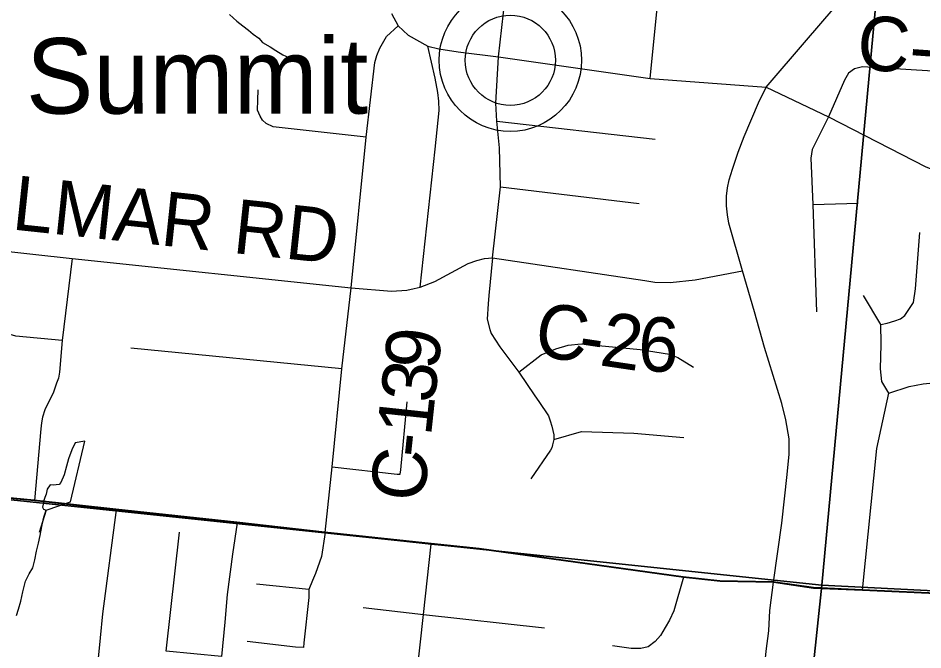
# Model space of a CAD drawing. Extents: x 0 to 34, y 0 to 22.
# Drawn here: x 6.917 to 7.863, y 17.176 to 17.836 of the extents above; entities that cross this region are included whole.
import ezdxf

# ---------------------------------------------------------------- set-up
doc = ezdxf.new("R2010")
doc.units = 0
for name, color, linetype in [('GM_X_Corporation', 7, 'Continuous'), ('GM_X_County_Road', 7, 'Continuous'), ('GM_X_County_Road_Text', 7, 'Continuous'), ('GM_X_Minor_Lake', 7, 'Continuous'), ('GM_X_Minor_River', 7, 'Continuous'), ('GM_X_Township_Road', 7, 'Continuous'), ('GM_X_Unincorporated', 7, 'Continuous'), ('GM_X_Unincorporated_Location', 7, 'Continuous'), ('GM_X_Unincorporated_Text', 7, 'Continuous')]:
    doc.layers.add(name, color=color, linetype=linetype)

msp = doc.modelspace()

# ---------------------------------------------------------------- linework, layer by layer
at = {"layer": 'GM_X_Corporation'}
for points in [[(6.84307, 18.37994), (7.85258, 18.26748), (7.75749, 17.24313), (6.72714, 17.3517)], [(8.84816, 18.18678), (8.74847, 17.19314), (7.75749, 17.24313), (7.85258, 18.26748)], [(7.75749, 17.24313), (7.65014, 16.22807), (6.62666, 16.41197), (6.72714, 17.3517)], [(7.75749, 17.24313), (8.74847, 17.19314), (8.6363, 16.19905), (7.65014, 16.22807)]]:
    msp.add_lwpolyline(points, close=True, dxfattribs=at)
for points in [[(7.88472, 17.23462), (7.79987, 17.23841), (7.74867, 17.24069), (7.70673, 17.24691), (7.65098, 17.24787), (7.61247, 17.25204), (7.39931, 17.28159), (7.34885, 17.28675), (7.23769, 17.29869), (7.1457, 17.30903), (7.01917, 17.32266), (6.93373, 17.33224), (6.84006, 17.34108)], [(6.84006, 17.34108), (6.93373, 17.33224), (7.01917, 17.32266), (7.1457, 17.30903), (7.23769, 17.29869), (7.34885, 17.28675), (7.39931, 17.28159), (7.61247, 17.25204), (7.65098, 17.24787), (7.70673, 17.24691), (7.74867, 17.24069), (7.79987, 17.23841), (7.88472, 17.23462)]]:
    msp.add_lwpolyline(points, dxfattribs=at)
at = {"layer": 'GM_X_County_Road'}
for points in [[(7.41322, 17.58549), (7.42151, 17.65967), (7.42032, 17.70014), (7.41776, 17.72831), (7.4167, 17.74711), (7.41945, 17.79527), (7.4265, 17.85697), (7.44478, 18.02293), (7.44666, 18.04738), (7.45969, 18.17701), (7.46344, 18.21088), (7.46748, 18.24286), (7.46904, 18.27488), (7.46779, 18.30339)], [(7.70697, 17.24639), (7.71559, 17.30819), (7.72121, 17.35902), (7.7233, 17.38006), (7.72343, 17.39627), (7.7199, 17.416), (7.71559, 17.43325), (7.69753, 17.49165), (7.6871, 17.52903), (7.67442, 17.57189), (7.6604, 17.62153), (7.65875, 17.63043), (7.6577, 17.63971), (7.65796, 17.64964), (7.65888, 17.65839), (7.6607, 17.66689), (7.664, 17.67815), (7.67011, 17.69564), (7.67639, 17.71223), (7.69115, 17.74725), (7.69945, 17.76374), (7.74153, 17.8129), (7.79923, 17.8803)], [(7.30756, 17.84076), (7.31436, 17.82777)], [(7.26544, 17.55413), (7.28098, 17.71156), (7.29013, 17.78934), (7.29211, 17.79691), (7.29522, 17.80448), (7.30212, 17.81675), (7.31436, 17.82777)], [(7.31436, 17.82777), (7.32494, 17.81811), (7.34532, 17.80663), (7.35681, 17.80376), (7.37704, 17.80059), (7.41945, 17.79527), (7.57816, 17.77285), (7.69945, 17.76374)], [(7.69945, 17.76374), (7.76457, 17.73263), (7.8665, 17.68027), (7.9818, 17.63515), (8.11775, 17.58195), (8.1642, 17.56378), (8.17662, 17.56002), (8.19243, 17.5572)], [(6.75503, 17.60853), (6.97346, 17.58459), (7.26544, 17.55413)], [(7.26544, 17.55413), (7.30756, 17.55061), (7.32343, 17.5515), (7.33128, 17.55316), (7.33755, 17.55467), (7.35273, 17.56056), (7.38769, 17.57952), (7.39668, 17.58247), (7.40489, 17.5846), (7.41322, 17.58549), (7.57234, 17.5615), (7.58292, 17.56007), (7.59885, 17.55964), (7.62509, 17.56235), (7.67442, 17.57189)], [(7.23793, 17.29817), (7.24557, 17.36694), (7.25562, 17.46923), (7.26544, 17.55413)], [(6.20646, 17.40492), (6.41909, 17.38524), (6.50244, 17.37752), (6.73053, 17.35234), (6.8403, 17.34056), (6.93397, 17.33172), (7.01941, 17.32214), (7.14594, 17.30851), (7.23793, 17.29817), (7.34909, 17.28622), (7.39955, 17.28107), (7.6127, 17.25151), (7.65122, 17.24735), (7.70697, 17.24639), (7.7489, 17.24017), (7.80011, 17.23789), (7.88496, 17.2341), (7.94383, 17.2315), (8.00436, 17.22967), (8.05662, 17.22809), (8.13919, 17.2232), (8.19428, 17.22143)], [(7.69325, 16.6628), (7.69899, 16.72501), (7.70539, 16.79178), (7.70605, 16.8089), (7.70507, 16.89642), (7.70788, 16.9367), (7.71154, 16.97968), (7.71187, 17.00938), (7.71193, 17.02124), (7.71128, 17.02803), (7.69808, 17.08723), (7.69612, 17.10722), (7.69454, 17.12257), (7.69459, 17.13179), (7.69716, 17.15269), (7.69923, 17.17425), (7.702, 17.19542), (7.70331, 17.21685), (7.70697, 17.24639)]]:
    msp.add_lwpolyline(points, dxfattribs=at)
at = {"layer": 'GM_X_Minor_Lake'}
for points in [[(6.9462, 17.32172), (6.97179, 17.33033), (6.98676, 17.39372), (6.97647, 17.3921), (6.97324, 17.38459), (6.96957, 17.37519), (6.96747, 17.36766), (6.96495, 17.35861), (6.96171, 17.35072), (6.95975, 17.3485), (6.95366, 17.3479), (6.95062, 17.34798), (6.94747, 17.34351), (6.94619, 17.33822), (6.94496, 17.33484)], [(6.94496, 17.33484), (6.94362, 17.33068), (6.94312, 17.32805), (6.94249, 17.32466), (6.94362, 17.32278), (6.9462, 17.32172)]]:
    msp.add_lwpolyline(points, dxfattribs=at)
at = {"layer": 'GM_X_Minor_River'}
for points in [[(7.13793, 17.83965), (7.14566, 17.83254), (7.15195, 17.82776), (7.15787, 17.82338), (7.16266, 17.81903), (7.16859, 17.81502), (7.17261, 17.81032), (7.18043, 17.80587), (7.18636, 17.80186), (7.1938, 17.79743), (7.20016, 17.79455)], [(6.91517, 17.21165), (6.9172, 17.21808), (6.91964, 17.2264), (6.92173, 17.23624), (6.92336, 17.24192), (6.92461, 17.2476), (6.92857, 17.25513), (6.9325, 17.26152), (6.93456, 17.26985), (6.93626, 17.27894), (6.93832, 17.28727), (6.93999, 17.29522), (6.9421, 17.3062), (6.94377, 17.31416), (6.9462, 17.32172), (6.9389, 17.29828)]]:
    msp.add_lwpolyline(points, dxfattribs=at)
at = {"layer": 'GM_X_Township_Road'}
for p, q in [((7.41776, 17.72831), (7.58338, 17.70935)), ((7.42151, 17.65967), (7.56639, 17.64228)), ((7.74816, 17.64096), (7.79541, 17.6423)), ((7.41322, 17.58549), (7.4094, 17.54615)), ((7.25562, 17.46923), (7.03492, 17.49093)), ((7.22112, 17.23863), (7.16626, 17.24435))]:
    msp.add_line(p, q, dxfattribs=at)
for points in [[(7.57816, 17.77285), (7.59263, 17.91973), (7.59462, 17.93764), (7.60527, 18.03351), (7.60738, 18.05697), (7.61338, 18.12019)], [(7.33755, 17.55467), (7.35329, 17.69889), (7.35725, 17.73923), (7.35694, 17.74901), (7.35605, 17.75814), (7.35303, 17.77309), (7.34532, 17.80663)], [(8.14057, 17.64298), (8.08032, 17.66555), (8.03464, 17.6817), (8.02698, 17.68624), (8.0213, 17.69111), (8.01796, 17.69874), (8.0173, 17.70863), (8.01819, 17.7204), (8.02148, 17.75104), (8.0197, 17.75881), (8.01636, 17.76373), (8.01152, 17.76837), (8.00427, 17.77161), (7.99805, 17.7728), (7.80019, 17.78511), (7.79183, 17.78272), (7.78561, 17.77842), (7.78142, 17.77089), (7.76457, 17.73263), (7.74735, 17.69868), (7.74591, 17.68936), (7.74816, 17.64096), (7.75208, 17.52888)], [(7.28098, 17.71156), (7.18385, 17.72219), (7.17645, 17.72582), (7.17267, 17.72914), (7.1701, 17.73352), (7.16739, 17.73956), (7.16754, 17.75013), (7.16799, 17.76086)], [(7.81924, 17.51564), (7.8259, 17.51691), (7.834, 17.51942), (7.83995, 17.52159), (7.84427, 17.52501), (7.84859, 17.53131), (7.85327, 17.53869), (7.85543, 17.55291), (7.86003, 17.61178)], [(6.97346, 17.58459), (6.96314, 17.49895), (6.9602, 17.46598), (6.95909, 17.45972), (6.95725, 17.45438), (6.95393, 17.4448), (6.94491, 17.42657), (6.94233, 17.41883), (6.94123, 17.41294), (6.94086, 17.4065), (6.93397, 17.33172)], [(7.4094, 17.54615), (7.40854, 17.5373), (7.40763, 17.52129), (7.41022, 17.5105), (7.41161, 17.50643), (7.42069, 17.49216), (7.44056, 17.466), (7.45746, 17.44102)], [(7.81969, 17.49881), (7.81978, 17.50268), (7.81942, 17.5088), (7.81924, 17.51564), (7.80105, 17.54607)], [(6.96314, 17.49895), (6.91452, 17.50337), (6.90384, 17.50668), (6.88966, 17.5111), (6.8484, 17.52455), (6.82004, 17.53376), (6.79278, 17.53744), (6.74809, 17.5416)], [(7.80011, 17.23789), (7.81506, 17.38615), (7.82752, 17.44398), (7.82014, 17.45604), (7.81902, 17.46923), (7.8196, 17.49493), (7.81969, 17.49881)], [(7.44056, 17.466), (7.46413, 17.48383), (7.47948, 17.49011), (7.49207, 17.49395), (7.50575, 17.49549), (7.56769, 17.48968), (7.59822, 17.48469), (7.60683, 17.48105), (7.62323, 17.47114)], [(7.82752, 17.44398), (7.84877, 17.45082), (7.86353, 17.4537), (7.87398, 17.45478), (7.89018, 17.4519), (7.91143, 17.4501), (7.96113, 17.44578), (7.98165, 17.43569), (8.02415, 17.40905), (8.09798, 17.37952), (8.16856, 17.35359), (8.1979, 17.34492)], [(7.24557, 17.36694), (7.31353, 17.35943), (7.31651, 17.35937), (7.31719, 17.3639), (7.3239, 17.43472)], [(7.45746, 17.44102), (7.46141, 17.43519), (7.47168, 17.42008), (7.47349, 17.4151), (7.47531, 17.40951), (7.47711, 17.40045), (7.47727, 17.3956), (7.4758, 17.38985), (7.47505, 17.3868), (7.47365, 17.38434), (7.45336, 17.35437)], [(7.47727, 17.3956), (7.50627, 17.40377), (7.56103, 17.40197), (7.61316, 17.39756)], [(7.01941, 17.32214), (7.00508, 17.21333), (7.00263, 17.18835), (6.99624, 17.12174), (6.98211, 16.9781), (6.97254, 16.87606)], [(7.14594, 17.30851), (7.14115, 17.27554), (7.13544, 17.23355), (7.13305, 17.20464), (7.12968, 17.16865), (7.0718, 17.1742), (7.08572, 17.29876)], [(7.23793, 17.29817), (7.23433, 17.27309), (7.22788, 17.25551), (7.22484, 17.24817), (7.22112, 17.23863), (7.22088, 17.23021), (7.21593, 17.1829), (7.21547, 17.1782), (7.20699, 17.17848), (7.15653, 17.18429)], [(7.32745, 17.09054), (7.33417, 17.15233), (7.3408, 17.21255), (7.34909, 17.28622)], [(7.6127, 17.25151), (7.60266, 17.21647), (7.59826, 17.2066), (7.59385, 17.19903), (7.58892, 17.19074), (7.58328, 17.18422), (7.57606, 17.17894), (7.5683, 17.177), (7.55808, 17.177), (7.53864, 17.17978)], [(7.27799, 17.21992), (7.3408, 17.21255), (7.46751, 17.19874)]]:
    msp.add_lwpolyline(points, dxfattribs=at)
at = {"layer": 'GM_X_Unincorporated'}
for radius in [0.0744, 0.04716]:
    msp.add_circle((7.43177, 17.79178), radius, dxfattribs=at)
at = {"layer": 'GM_X_Unincorporated_Location'}
msp.add_line((7.43177, 17.79178), (7.43177, 17.79178), dxfattribs=at)

# ---------------------------------------------------------------- texts
at = {"layer": 'GM_X_County_Road_Text'}
for s, height, rotation, p in [('C-126', 0.056818, 355.87541, (7.79307, 17.78258)), ('JULMAR RD', 0.056818, 353.92776, (6.81703, 17.62493)), ('C', 0.05682, 351.42744, (7.45504, 17.48357)), ('2', 0.05682, 351.55156, (7.52384, 17.47321)), ('6', 0.05682, 357.28433, (7.56436, 17.4675)), ('9', 0.05682, 83.91941, (7.35613, 17.46709)), ('-', 0.05682, 351.44313, (7.50086, 17.47667)), ('3', 0.05682, 83.88705, (7.35243, 17.43253)), ('1', 0.05682, 83.86916, (7.34872, 17.39798)), ('-', 0.05682, 83.86615, (7.34624, 17.37499)), ('C', 0.05682, 83.86597, (7.3413, 17.32893))]:
    msp.add_text(s, height=height, rotation=rotation, dxfattribs=at).set_placement(p)
at = {"layer": 'GM_X_Unincorporated_Text'}
msp.add_text('Summit', height=0.078977, rotation=0.00001, dxfattribs=at).set_placement((6.92517, 17.736))

doc.saveas('drawing.dxf')
